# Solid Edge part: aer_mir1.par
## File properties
Author: Kasutaja
Template: Ansi Inch Part.par
Last saved by: Kasutaja
Revision: 2
Application: Solid Edge
Accuracy: 0,990
Username: Kasutaja
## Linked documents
aer.par
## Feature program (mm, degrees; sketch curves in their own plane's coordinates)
part copy "CopiedPart_1"
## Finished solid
Body 1: solid body, 8 faces, 12 edges, 6 vertices.
  Faces by surface: blend 3, spline 3, plane 2
  Edges by curve: curve on surface 6, intersection 6
Bounding box of the edges (mm; curved faces can reach further): 9.363 x 230.812 x 18.909, from (-4.6814, 0, -9.4545) to (4.6813, 230.8122, 9.4544).
Planar faces by outward normal: +y 1, -y 1
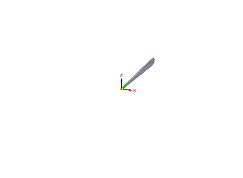
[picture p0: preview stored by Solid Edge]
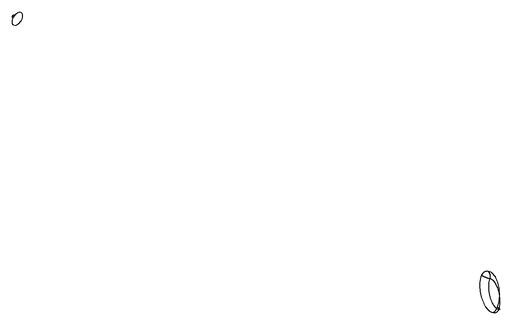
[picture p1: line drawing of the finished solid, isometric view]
